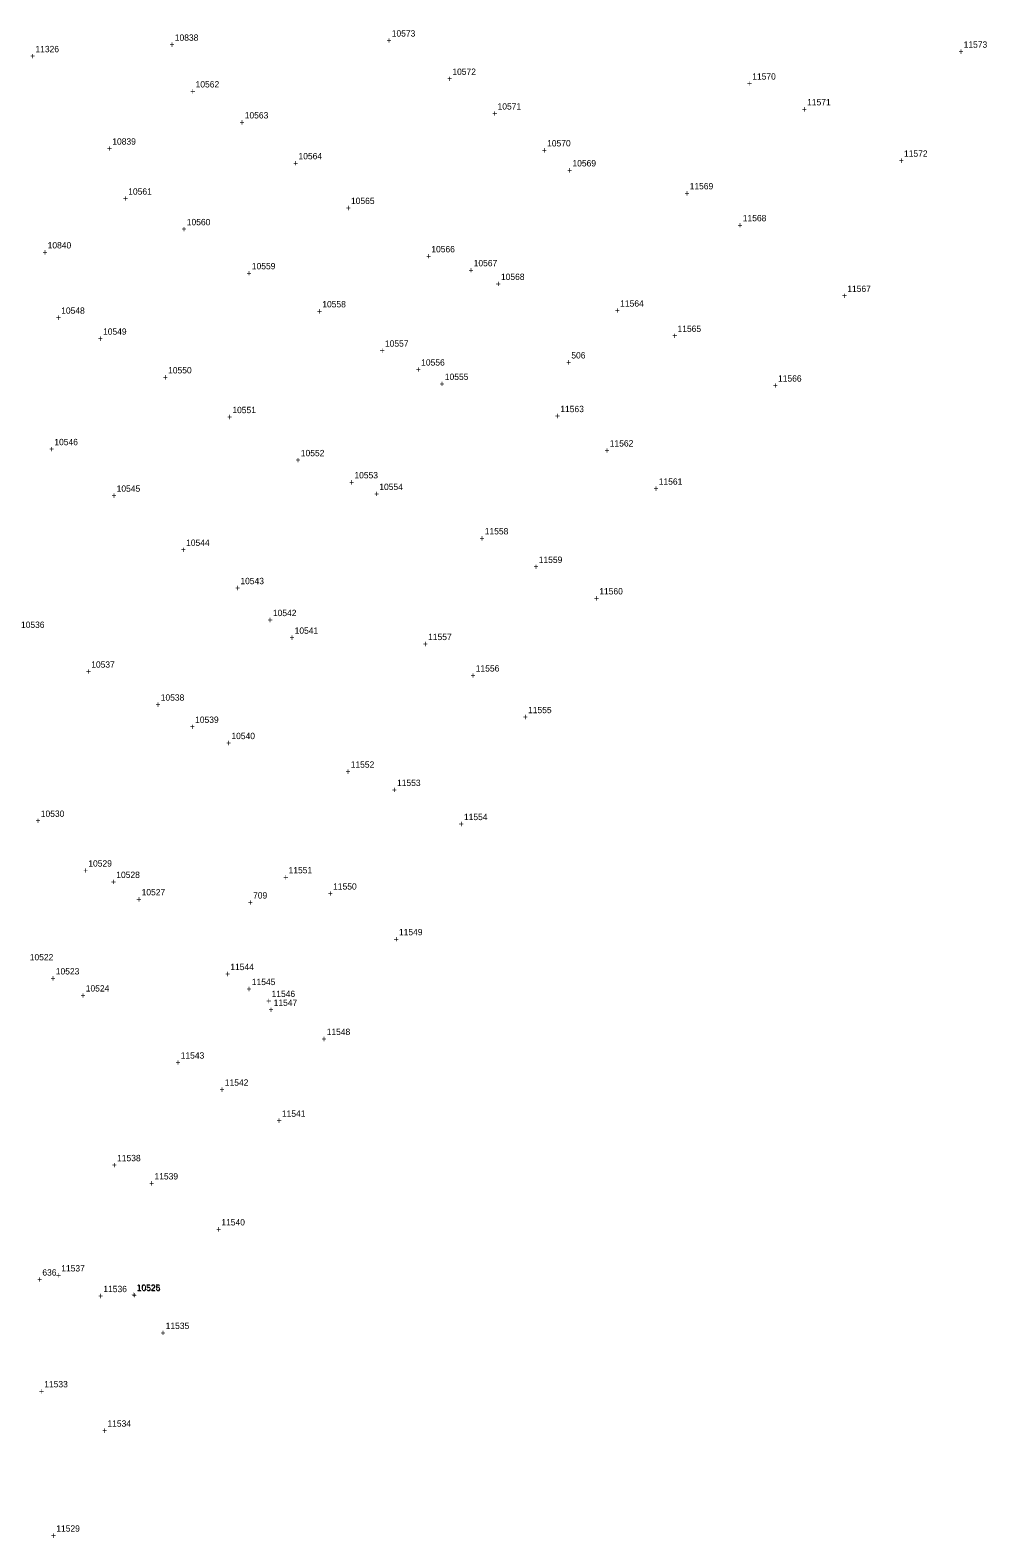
# Model space of a CAD drawing. Extents: x 1160051 to 1162814, y 614604 to 619560.
# Drawn here: x 1161781 to 1162158, y 617733 to 618327 of the extents above; entities that cross this region are included whole.
import ezdxf

# ---------------------------------------------------------------- set-up
doc = ezdxf.new("R2010")
doc.units = 0
for name, color, linetype in [('S_Control_Temp_Traverse', 7, 'Continuous'), ('S_Control_Traverse_Point', 7, 'Continuous'), ('S_Drainage_Culvert_Top', 7, 'Continuous'), ('S_Drainage_Invert', 7, 'Continuous'), ('S_Ground_Elevation', 7, 'Continuous'), ('S_Traffic_Sign_DoublePost', 7, 'Continuous')]:
    doc.layers.add(name, color=color, linetype=linetype)

msp = doc.modelspace()

# ---------------------------------------------------------------- texts
at = {"layer": 'S_Control_Temp_Traverse'}
for s, p in [('+', (1161783.34, 617833.27)), ('636', (1161785.4, 617836.02))]:
    msp.add_text(s, height=2.5, dxfattribs=at).set_placement(p)
at = {"layer": 'S_Control_Traverse_Point'}
for s, p in [('+', (1161992, 618194.93)), ('+', (1161992, 618194.93)), ('+', (1161992, 618194.93)), ('+', (1161992, 618194.93)), ('+', (1161992, 618194.93)), ('+', (1161992, 618194.93)), ('+', (1161992, 618194.93)), ('+', (1161992, 618194.93)), ('506', (1161994.06, 618197.68)), ('506', (1161994.06, 618197.68)), ('506', (1161994.06, 618197.68)), ('506', (1161994.06, 618197.68)), ('506', (1161994.06, 618197.68)), ('506', (1161994.06, 618197.68)), ('506', (1161994.06, 618197.68)), ('506', (1161994.06, 618197.68)), ('+', (1161866.47, 617981.96)), ('+', (1161866.47, 617981.96)), ('+', (1161866.47, 617981.96)), ('+', (1161866.47, 617981.96)), ('+', (1161866.47, 617981.96)), ('+', (1161866.47, 617981.96)), ('+', (1161866.47, 617981.96)), ('+', (1161866.47, 617981.96)), ('+', (1161866.47, 617981.96)), ('+', (1161866.47, 617981.96)), ('709', (1161868.53, 617984.7)), ('709', (1161868.53, 617984.7)), ('709', (1161868.53, 617984.7)), ('709', (1161868.53, 617984.7)), ('709', (1161868.53, 617984.7)), ('709', (1161868.53, 617984.7)), ('709', (1161868.53, 617984.7)), ('709', (1161868.53, 617984.7)), ('709', (1161868.53, 617984.7)), ('709', (1161868.53, 617984.7))]:
    msp.add_text(s, height=2.5, dxfattribs=at).set_placement(p)
at = {"layer": 'S_Drainage_Culvert_Top'}
for s, p in [('+', (1161820.52, 617827.36)), ('10525', (1161822.58, 617830.11))]:
    msp.add_text(s, height=2.5, dxfattribs=at).set_placement(p)
at = {"layer": 'S_Drainage_Invert'}
for s, p in [('+', (1161820.69, 617827.09)), ('10526', (1161822.75, 617829.84))]:
    msp.add_text(s, height=2.5, dxfattribs=at).set_placement(p)
at = {"layer": 'S_Ground_Elevation'}
for s, p in [('10573', (1161923.23, 618324.62)), ('+', (1161835.59, 618320.21)), ('10838', (1161837.66, 618322.96)), ('+', (1161921.16, 618321.87)), ('11573', (1162148.81, 618320.21)), ('+', (1161780.63, 618315.7)), ('11326', (1161782.69, 618318.45)), ('+', (1162146.75, 618317.46)), ('10572', (1161947.14, 618309.51)), ('11570', (1162065.42, 618307.64)), ('+', (1161843.8, 618301.8)), ('10562', (1161845.86, 618304.55)), ('+', (1161945.08, 618306.76)), ('+', (1162063.36, 618304.89)), ('10571', (1161964.96, 618295.85)), ('11571', (1162087.07, 618297.49)), ('+', (1161863.18, 618289.58)), ('10563', (1161865.24, 618292.33)), ('+', (1161962.89, 618293.1)), ('+', (1162085.01, 618294.74)), ('+', (1161810.94, 618279.26)), ('10839', (1161813, 618282.01)), ('+', (1161982.44, 618278.55)), ('10570', (1161984.5, 618281.3)), ('11572', (1162125.28, 618277.23)), ('+', (1161884.38, 618273.48)), ('10564', (1161886.44, 618276.23)), ('10569', (1161994.51, 618273.41)), ('+', (1162123.21, 618274.48)), ('+', (1161992.45, 618270.66)), ('+', (1161817.21, 618259.53)), ('10561', (1161819.27, 618262.28)), ('+', (1162038.69, 618261.62)), ('11569', (1162040.75, 618264.37)), ('+', (1161905.09, 618255.84)), ('10565', (1161907.15, 618258.59)), ('10560', (1161842.38, 618250.22)), ('+', (1162059.63, 618249.04)), ('11568', (1162061.69, 618251.79)), ('+', (1161840.32, 618247.47)), ('+', (1161785.44, 618238.32)), ('10840', (1161787.5, 618241.07)), ('+', (1161936.78, 618236.79)), ('10566', (1161938.84, 618239.54)), ('+', (1161865.98, 618230.1)), ('10559', (1161868.04, 618232.85)), ('+', (1161953.49, 618231.29)), ('10567', (1161955.55, 618234.04)), ('+', (1161964.24, 618225.89)), ('10568', (1161966.3, 618228.64)), ('11567', (1162102.91, 618223.93)), ('10558', (1161895.84, 618217.82)), ('11564', (1162013.33, 618218.12)), ('+', (1162100.85, 618221.18)), ('+', (1161790.78, 618212.56)), ('10548', (1161792.84, 618215.31)), ('+', (1161893.77, 618215.07)), ('+', (1162011.27, 618215.37)), ('10549', (1161809.35, 618207.04)), ('11565', (1162035.95, 618208.16)), ('+', (1161807.29, 618204.29)), ('10557', (1161920.54, 618202.32)), ('+', (1162033.89, 618205.41)), ('+', (1161918.48, 618199.57)), ('10556', (1161934.83, 618194.88)), ('+', (1161832.95, 618189.04)), ('10550', (1161835.01, 618191.79)), ('+', (1161932.77, 618192.13)), ('10555', (1161944.16, 618189.21)), ('11566', (1162075.59, 618188.56)), ('+', (1161942.1, 618186.46)), ('+', (1162073.53, 618185.81)), ('10551', (1161860.36, 618176.12)), ('11563', (1161989.71, 618176.51)), ('+', (1161858.3, 618173.37)), ('+', (1161987.65, 618173.76)), ('+', (1161788.08, 618160.73)), ('10546', (1161790.14, 618163.48)), ('10552', (1161887.36, 618159.13)), ('+', (1162007.17, 618160.21)), ('11562', (1162009.23, 618162.96)), ('+', (1161885.3, 618156.38)), ('+', (1161906.44, 618147.64)), ('10553', (1161908.5, 618150.39)), ('11561', (1162028.55, 618147.88)), ('+', (1161812.66, 618142.37)), ('10545', (1161814.72, 618145.12)), ('+', (1161916.26, 618143.07)), ('10554', (1161918.32, 618145.82)), ('+', (1162026.49, 618145.13)), ('11558', (1161959.91, 618128.3)), ('10544', (1161842.11, 618123.79)), ('+', (1161957.85, 618125.55)), ('+', (1161840.05, 618121.04)), ('11559', (1161981.21, 618117.07)), ('+', (1161979.15, 618114.32)), ('+', (1161861.46, 618105.93)), ('10543', (1161863.52, 618108.68)), ('11560', (1162005.09, 618104.63)), ('+', (1162003.03, 618101.88)), ('+', (1161874.28, 618093.33)), ('10542', (1161876.34, 618096.08)), ('10536', (1161776.97, 618091.44)), ('10541', (1161884.93, 618089.11)), ('+', (1161882.87, 618086.36)), ('+', (1161935.5, 618083.88)), ('11557', (1161937.56, 618086.63)), ('10537', (1161804.68, 618075.76)), ('+', (1161802.62, 618073.01)), ('+', (1161954.31, 618071.48)), ('11556', (1161956.37, 618074.23)), ('+', (1161830.04, 618059.99)), ('10538', (1161832.11, 618062.74)), ('11555', (1161976.99, 618057.81)), ('10539', (1161845.66, 618053.98)), ('+', (1161974.93, 618055.06)), ('+', (1161843.6, 618051.23)), ('10540', (1161859.98, 618047.57)), ('+', (1161857.92, 618044.82)), ('11552', (1161907.04, 618036.28)), ('+', (1161904.98, 618033.53)), ('11553', (1161925.31, 618029.1)), ('+', (1161923.25, 618026.35)), ('10530', (1161784.79, 618016.92)), ('11554', (1161951.71, 618015.64)), ('+', (1161782.73, 618014.17)), ('+', (1161949.65, 618012.89)), ('+', (1161801.48, 617994.56)), ('10529', (1161803.54, 617997.31)), ('10528', (1161814.57, 617992.82)), ('11551', (1161882.53, 617994.63)), ('+', (1161812.51, 617990.07)), ('10527', (1161824.57, 617985.95)), ('+', (1161880.47, 617991.88)), ('11550', (1161900.1, 617988.25)), ('+', (1161822.51, 617983.2)), ('+', (1161898.04, 617985.5)), ('11549', (1161926.07, 617970.23)), ('+', (1161924.01, 617967.48)), ('10522', (1161780.44, 617960.34)), ('11544', (1161859.55, 617956.49)), ('+', (1161788.65, 617952.02)), ('10523', (1161790.71, 617954.77)), ('+', (1161857.49, 617953.74)), ('+', (1161800.47, 617945.3)), ('10524', (1161802.53, 617948.05)), ('+', (1161874.59, 617939.64)), ('11547', (1161876.65, 617942.39)), ('+', (1161895.51, 617928.14)), ('11548', (1161897.57, 617930.89)), ('11543', (1161839.99, 617921.59)), ('+', (1161837.93, 617918.84)), ('11542', (1161857.39, 617910.91)), ('+', (1161855.33, 617908.16)), ('11541', (1161879.89, 617898.64)), ('+', (1161877.83, 617895.89)), ('11538', (1161814.89, 617881.13)), ('+', (1161812.83, 617878.38)), ('11539', (1161829.64, 617873.93)), ('+', (1161827.57, 617871.18)), ('11540', (1161856.02, 617855.8)), ('+', (1161853.96, 617853.05)), ('11537', (1161792.87, 617837.65)), ('+', (1161790.81, 617834.9)), ('+', (1161807.41, 617826.74)), ('11536', (1161809.47, 617829.49)), ('11535', (1161834.05, 617814.98)), ('+', (1161831.99, 617812.23)), ('11533', (1161786.15, 617791.95)), ('+', (1161784.09, 617789.2)), ('+', (1161809.02, 617773.68)), ('11534', (1161811.08, 617776.43)), ('+', (1161788.85, 617732.29)), ('11529', (1161790.91, 617735.04))]:
    msp.add_text(s, height=2.5, dxfattribs=at).set_placement(p)
at = {"layer": 'S_Traffic_Sign_DoublePost'}
for s, p in [('11545', (1161868.03, 617950.58)), ('+', (1161865.97, 617947.83)), ('11546', (1161875.82, 617945.87)), ('+', (1161873.76, 617943.12))]:
    msp.add_text(s, height=2.5, dxfattribs=at).set_placement(p)

doc.saveas('drawing.dxf')
